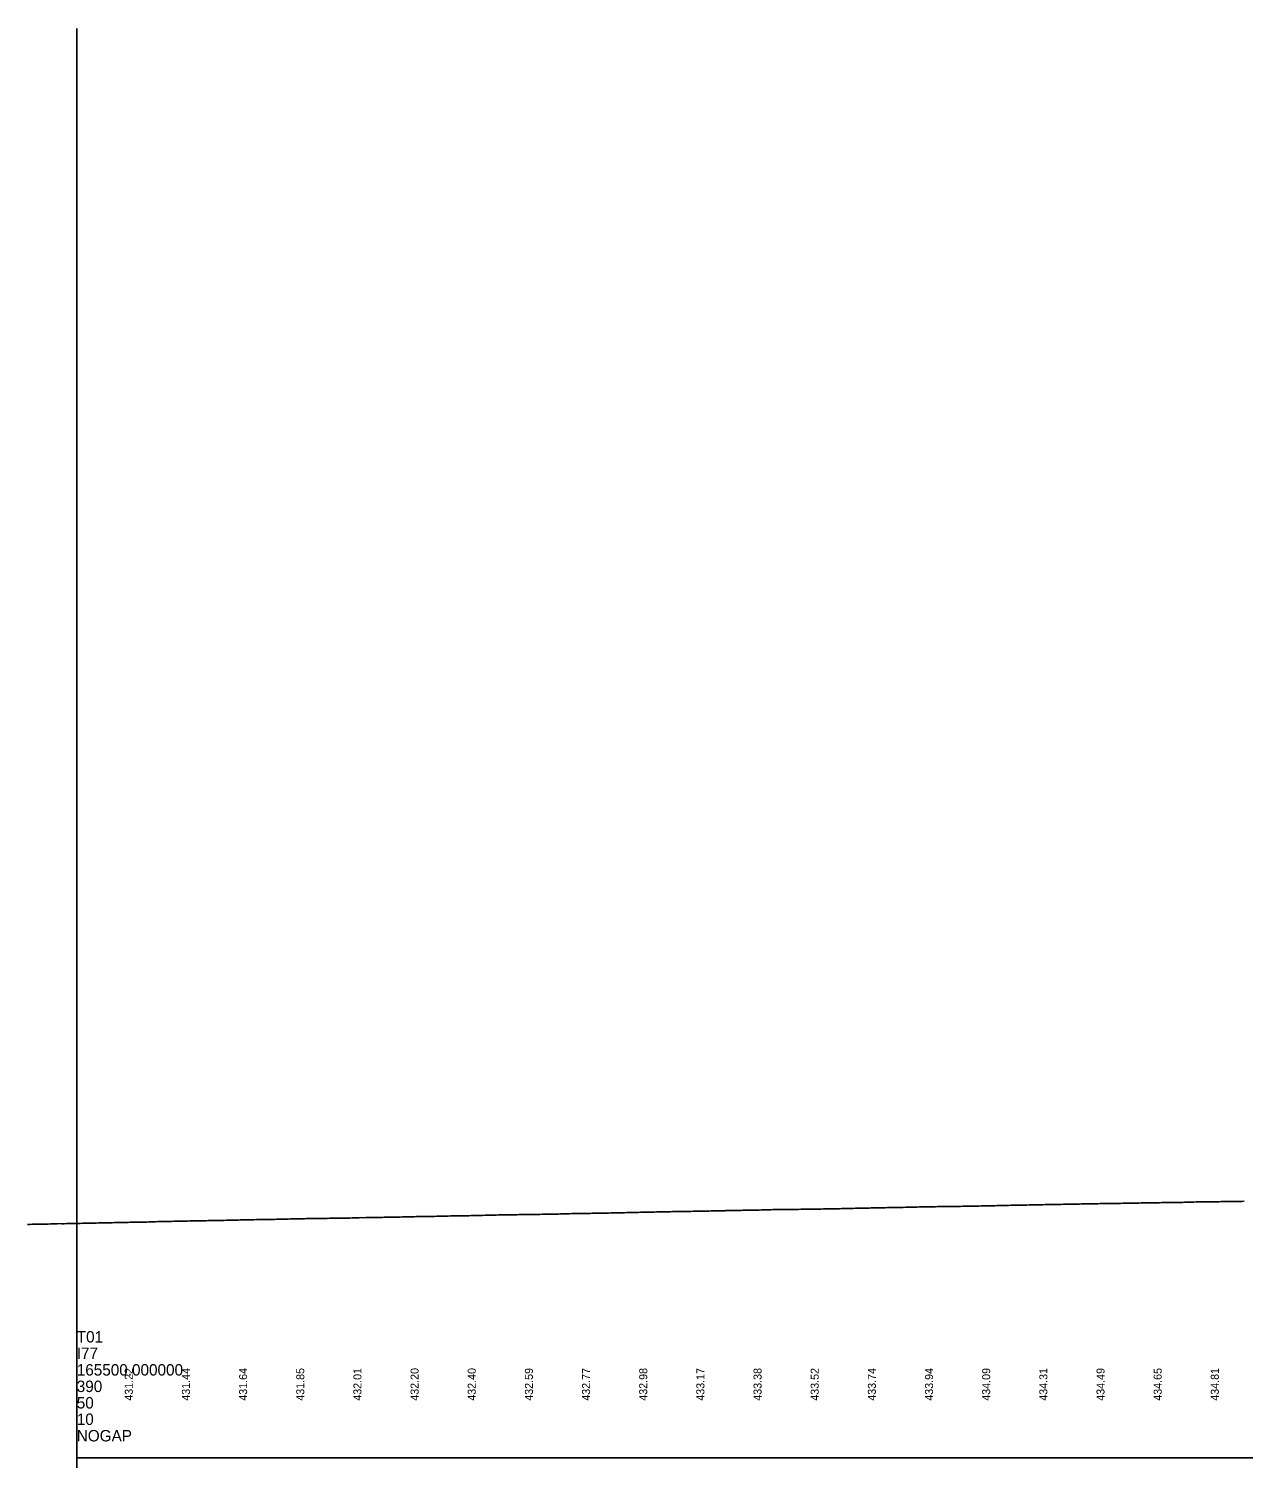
# Model space of a CAD drawing. Extents: x 2017200 to 2047700, y 854850 to 893350.
# Drawn here: x 2020458 to 2021520, y 856100 to 857350 of the extents above; entities that cross this region are included whole.
import ezdxf

# ---------------------------------------------------------------- set-up
doc = ezdxf.new("R2010")
doc.units = 0
for name, color, linetype in [('RD_DDB_Profile_EX', 7, 'Continuous'), ('RD_DDB_StripGrade', 7, 'Continuous'), ('RD_GPK_Profile_Cell', 7, 'Continuous')]:
    doc.layers.add(name, color=color, linetype=linetype)

msp = doc.modelspace()

# ---------------------------------------------------------------- linework, layer by layer
at = {"layer": 'RD_DDB_Profile_EX'}
msp.add_lwpolyline([(2020456.9, 856304.2), (2020458.9, 856304.2), (2020460.9, 856304.3), (2020462.9, 856304.3), (2020464.9, 856304.3), (2020466.9, 856304.4), (2020468.9, 856304.4), (2020471, 856304.5), (2020472.9, 856304.5), (2020474.9, 856304.5), (2020477, 856304.6), (2020479, 856304.6), (2020481, 856304.7), (2020482.9, 856304.7), (2020484.9, 856304.9), (2020487, 856304.8), (2020488.9, 856304.8), (2020490.9, 856304.9), (2020493, 856304.9), (2020495, 856305), (2020497.1, 856305), (2020499, 856305.1), (2020501, 856305.1), (2020503.1, 856305.1), (2020505, 856305.2), (2020507, 856305.2), (2020507.3, 856305.3), (2020508.9, 856305.3), (2020510.5, 856305.3), (2020510.9, 856305.3), (2020512.9, 856305.3), (2020513.2, 856305.3), (2020515, 856305.4), (2020516.9, 856305.4), (2020519.1, 856305.5), (2020520.6, 856305.5), (2020521, 856305.5), (2020523, 856305.5), (2020524.8, 856305.6), (2020525.1, 856305.6), (2020527, 856305.6), (2020529, 856305.7), (2020529.3, 856305.7), (2020531.1, 856305.7), (2020533, 856305.8), (2020534.9, 856305.8), (2020535.2, 856305.8), (2020536.9, 856305.8), (2020538.9, 856305.9), (2020539.4, 856305.9), (2020541, 856305.9), (2020543, 856305.9), (2020545.1, 856306), (2020546.6, 856306.1), (2020547, 856306.1), (2020549, 856306.1), (2020551.1, 856306.1), (2020553, 856306.1), (2020555.2, 856306.2), (2020557.1, 856306.3), (2020559, 856306.3), (2020561.1, 856306.3), (2020562.9, 856306.4), (2020564.9, 856306.5), (2020565.3, 856306.5), (2020567, 856306.5), (2020569, 856306.5), (2020570.9, 856306.6), (2020573, 856306.7), (2020575, 856306.7), (2020577.1, 856306.7), (2020579, 856306.7), (2020581, 856306.8), (2020583, 856306.8), (2020584.9, 856306.9), (2020585.7, 856306.9), (2020586.9, 856306.9), (2020589, 856307), (2020591, 856307), (2020593, 856307.1), (2020595, 856307.1), (2020597, 856307.1), (2020599, 856307.2), (2020601, 856307.2), (2020603.1, 856307.3), (2020605.1, 856307.2), (2020606.9, 856307.3), (2020609.1, 856307.3), (2020611, 856307.4), (2020613, 856307.4), (2020615, 856307.5), (2020617, 856307.5), (2020619, 856307.5), (2020621, 856307.5), (2020623, 856307.6), (2020625, 856307.6), (2020627.1, 856307.7), (2020629, 856307.7), (2020631, 856307.8), (2020631.9, 856307.8), (2020633, 856307.8), (2020635, 856307.9), (2020637, 856307.9), (2020639, 856307.9), (2020641.1, 856308), (2020643, 856308.1), (2020644.9, 856308.2), (2020645.3, 856308.2), (2020647, 856308.2), (2020649, 856308.2), (2020651.2, 856308.2), (2020653, 856308.3), (2020655, 856308.3), (2020657.1, 856308.4), (2020659, 856308.4), (2020661, 856308.4), (2020663, 856308.5), (2020665, 856308.5), (2020667.1, 856308.6), (2020669, 856308.6), (2020671.3, 856308.6), (2020673, 856308.6), (2020674.7, 856308.7), (2020675, 856308.7), (2020677.2, 856308.7), (2020679, 856308.8), (2020681, 856308.8), (2020683.1, 856308.9), (2020685, 856308.9), (2020687, 856309), (2020689.1, 856309), (2020691, 856309.1), (2020693.1, 856309.1), (2020695, 856309.2), (2020697, 856309.2), (2020699.1, 856309.2), (2020701, 856309.3), (2020703, 856309.3), (2020705, 856309.3), (2020707, 856309.4), (2020709, 856309.4), (2020711, 856309.4), (2020713, 856309.5), (2020715.1, 856309.5), (2020717, 856309.5), (2020719, 856309.5), (2020721, 856309.6), (2020723, 856309.6), (2020725.1, 856309.6), (2020727, 856309.6), (2020729, 856309.7), (2020731, 856309.7), (2020733, 856309.7), (2020735, 856309.8), (2020737, 856309.8), (2020739, 856309.8), (2020741, 856309.9), (2020742.9, 856309.9), (2020745, 856310), (2020747, 856310), (2020749, 856310.1), (2020751, 856310), (2020753, 856310.1), (2020755, 856310.1), (2020757, 856310.2), (2020758.7, 856310.2), (2020761, 856310.2), (2020763, 856310.2), (2020765, 856310.3), (2020767, 856310.3), (2020769, 856310.4), (2020771, 856310.4), (2020772.5, 856310.4), (2020773, 856310.4), (2020775, 856310.4), (2020777, 856310.5), (2020779, 856310.5), (2020781, 856310.6), (2020783, 856310.6), (2020785, 856310.7), (2020787, 856310.7), (2020789, 856310.8), (2020791, 856310.8), (2020792.2, 856310.8), (2020793, 856310.9), (2020795, 856310.9), (2020797, 856311), (2020799, 856311), (2020801, 856311), (2020803, 856311.1), (2020805, 856311.1), (2020807, 856311.2), (2020809, 856311.2), (2020809.6, 856311.2), (2020811, 856311.2), (2020813, 856311.2), (2020815, 856311.3), (2020817, 856311.3), (2020819, 856311.4), (2020821, 856311.4), (2020823, 856311.5), (2020825, 856311.5), (2020827, 856311.6), (2020829, 856311.6), (2020831, 856311.6), (2020833, 856311.6), (2020835, 856311.7), (2020836.4, 856311.7), (2020837, 856311.7), (2020839, 856311.8), (2020841, 856311.8), (2020843, 856311.8), (2020845, 856311.9), (2020847.1, 856311.9), (2020849, 856312), (2020851, 856312), (2020853, 856312.1), (2020855, 856312.1), (2020857.1, 856312.2), (2020859, 856312.2), (2020861, 856312.3), (2020863, 856312.3), (2020865, 856312.3), (2020867, 856312.4), (2020869, 856312.5), (2020871, 856312.5), (2020873, 856312.5), (2020875.1, 856312.6), (2020877, 856312.6), (2020879.2, 856312.6), (2020881.1, 856312.6), (2020883.1, 856312.7), (2020883.5, 856312.7), (2020885.2, 856312.7), (2020887.1, 856312.8), (2020889, 856312.8), (2020889.3, 856312.8), (2020891, 856312.8), (2020893, 856312.8), (2020895.1, 856312.9), (2020896.7, 856312.9), (2020897, 856312.9), (2020899, 856312.9), (2020901.1, 856313), (2020903, 856313), (2020905.1, 856313), (2020907, 856313.1), (2020909, 856313.1), (2020911.1, 856313.1), (2020913.1, 856313.2), (2020915, 856313.2), (2020915.3, 856313.2), (2020917, 856313.2), (2020919, 856313.3), (2020921.3, 856313.3), (2020923.1, 856313.4), (2020925, 856313.4), (2020927.2, 856313.4), (2020929.1, 856313.5), (2020931, 856313.5), (2020933.1, 856313.6), (2020935.1, 856313.6), (2020936.9, 856313.6), (2020937.3, 856313.6), (2020939.1, 856313.7), (2020941.1, 856313.7), (2020941.6, 856313.7), (2020943, 856313.7), (2020944.5, 856313.7), (2020945, 856313.7), (2020947, 856313.8), (2020947.4, 856313.8), (2020949.1, 856313.8), (2020950.7, 856313.9), (2020951, 856313.9), (2020953.3, 856313.9), (2020954.7, 856313.9), (2020955.1, 856313.9), (2020957.1, 856314), (2020958.9, 856314), (2020959.2, 856314), (2020961.1, 856314.1), (2020963.1, 856314.1), (2020963.5, 856314.1), (2020964.9, 856314.1), (2020965.2, 856314.1), (2020967.1, 856314.2), (2020969, 856314.2), (2020969.4, 856314.2), (2020971, 856314.3), (2020973, 856314.3), (2020975.1, 856314.3), (2020976.7, 856314.4), (2020977, 856314.4), (2020979, 856314.4), (2020981.1, 856314.5), (2020983, 856314.5), (2020985.2, 856314.6), (2020987.1, 856314.6), (2020989.1, 856314.7), (2020991.2, 856314.7), (2020993.1, 856314.8), (2020995, 856314.8), (2020995.3, 856314.8), (2020997, 856314.9), (2020998.7, 856314.9), (2020999, 856314.9), (2021001.1, 856314.9), (2021002.6, 856315), (2021003.1, 856315), (2021005, 856315), (2021007.1, 856315.1), (2021009.1, 856315.1), (2021011.3, 856315.1), (2021013.1, 856315.2), (2021015.1, 856315.2), (2021017.2, 856315.3), (2021019.1, 856315.3), (2021021.2, 856315.4), (2021023, 856315.4), (2021025, 856315.4), (2021027.1, 856315.5), (2021029, 856315.5), (2021031, 856315.6), (2021033.1, 856315.6), (2021035.1, 856315.6), (2021037, 856315.6), (2021039.1, 856315.7), (2021041.1, 856315.7), (2021043.3, 856315.7), (2021045.1, 856315.8), (2021047.1, 856315.8), (2021049.2, 856315.8), (2021051, 856315.9), (2021053.1, 856315.9), (2021055, 856316), (2021057, 856316), (2021058, 856316), (2021059, 856316), (2021061.1, 856316.1), (2021063.1, 856316.2), (2021065.1, 856316.2), (2021067, 856316.2), (2021067.7, 856316.3), (2021069.1, 856316.3), (2021071.1, 856316.3), (2021073.1, 856316.4), (2021075, 856316.4), (2021075.3, 856316.4), (2021077, 856316.5), (2021078.7, 856316.5), (2021079, 856316.5), (2021079.6, 856316.5), (2021081.1, 856316.5), (2021082.6, 856316.6), (2021083, 856316.6), (2021085, 856316.6), (2021087.1, 856316.7), (2021089.1, 856316.7), (2021091.2, 856316.7), (2021093.1, 856316.8), (2021095, 856316.8), (2021097, 856316.8), (2021099, 856316.9), (2021101.1, 856316.9), (2021103, 856316.9), (2021105, 856317), (2021107.1, 856317), (2021109, 856317.1), (2021111, 856317.1), (2021113.1, 856317.1), (2021115.1, 856317.2), (2021117.3, 856317.2), (2021118.8, 856317.2), (2021119.2, 856317.2), (2021121.1, 856317.3), (2021122.9, 856317.3), (2021123.3, 856317.3), (2021125.2, 856317.3), (2021127.1, 856317.3), (2021127.6, 856317.3), (2021129, 856317.3), (2021130.5, 856317.3), (2021131, 856317.3), (2021133.3, 856317.4), (2021135, 856317.4), (2021137, 856317.4), (2021139.1, 856317.4), (2021141, 856317.5), (2021143, 856317.5), (2021145, 856317.6), (2021147, 856317.6), (2021149.1, 856317.6), (2021151.1, 856317.6), (2021153.1, 856317.7), (2021155.1, 856317.7), (2021157.1, 856317.7), (2021159.2, 856317.8), (2021161.1, 856317.8), (2021163, 856317.9), (2021165.2, 856317.9), (2021167.1, 856317.9), (2021169, 856318), (2021171.1, 856318), (2021173.1, 856318.1), (2021175, 856318.1), (2021177.1, 856318.2), (2021179.1, 856318.2), (2021181.1, 856318.3), (2021183.1, 856318.3), (2021185.1, 856318.4), (2021187, 856318.4), (2021189, 856318.5), (2021191, 856318.5), (2021193.1, 856318.5), (2021195, 856318.6), (2021197.1, 856318.6), (2021199.1, 856318.7), (2021201.1, 856318.7), (2021203.1, 856318.7), (2021205.1, 856318.8), (2021207.2, 856318.8), (2021209.1, 856318.9), (2021211.1, 856318.9), (2021213.2, 856318.9), (2021215, 856319), (2021217, 856319), (2021219.1, 856319.1), (2021221.1, 856319.1), (2021223, 856319.1), (2021225.1, 856319.2), (2021227.1, 856319.3), (2021229.1, 856319.3), (2021231.1, 856319.3), (2021233.3, 856319.4), (2021235.2, 856319.4), (2021237.1, 856319.5), (2021239.3, 856319.5), (2021241, 856319.5), (2021243, 856319.6), (2021244.8, 856319.6), (2021245.2, 856319.6), (2021246.7, 856319.7), (2021247.1, 856319.7), (2021249.1, 856319.7), (2021251.1, 856319.7), (2021253.1, 856319.8), (2021255.1, 856319.8), (2021257.1, 856319.8), (2021259.1, 856319.8), (2021261.1, 856319.9), (2021262.1, 856319.9), (2021263.1, 856319.9), (2021265.1, 856319.9), (2021266.6, 856320), (2021267, 856320), (2021269, 856320), (2021271.2, 856320), (2021273.1, 856320), (2021275.1, 856320.1), (2021277.2, 856320.1), (2021279.1, 856320.1), (2021281.1, 856320.1), (2021281.5, 856320.1), (2021282.8, 856320.2), (2021283.2, 856320.2), (2021285.1, 856320.2), (2021287, 856320.2), (2021287.4, 856320.2), (2021289.2, 856320.2), (2021291.1, 856320.3), (2021291.6, 856320.3), (2021293.1, 856320.3), (2021294.7, 856320.3), (2021295, 856320.3), (2021297.2, 856320.4), (2021299.1, 856320.4), (2021301.1, 856320.5), (2021302.2, 856320.5), (2021303.1, 856320.5), (2021305.1, 856320.6), (2021307.1, 856320.6), (2021309.1, 856320.7), (2021311.1, 856320.7), (2021312.1, 856320.7), (2021313.1, 856320.8), (2021315.1, 856320.8), (2021317.1, 856320.9), (2021319.2, 856320.9), (2021321, 856320.9), (2021323.3, 856321), (2021325.1, 856321), (2021327.1, 856321.1), (2021329.1, 856321.1), (2021331.1, 856321.1), (2021333.1, 856321.2), (2021335.2, 856321.2), (2021337.1, 856321.3), (2021339.1, 856321.3), (2021341.1, 856321.3), (2021341.8, 856321.4), (2021343.1, 856321.4), (2021345.1, 856321.4), (2021347.1, 856321.5), (2021349.1, 856321.5), (2021351.1, 856321.6), (2021353.1, 856321.6), (2021355.1, 856321.6), (2021356.6, 856321.7), (2021357.1, 856321.7), (2021359.1, 856321.7), (2021361.1, 856321.7), (2021363.1, 856321.8), (2021365.1, 856321.8), (2021367.1, 856321.9), (2021369.1, 856321.9), (2021371.1, 856322), (2021373.3, 856322), (2021375.1, 856322), (2021377.1, 856322), (2021378.8, 856322.1), (2021381.1, 856322.1), (2021383.1, 856322.2), (2021385.1, 856322.2), (2021387.1, 856322.2), (2021389.1, 856322.2), (2021391.1, 856322.3), (2021393.2, 856322.3), (2021395.1, 856322.4), (2021397.1, 856322.4), (2021399.1, 856322.4), (2021401.1, 856322.4), (2021403.2, 856322.5), (2021405.1, 856322.5), (2021407.1, 856322.5), (2021409.1, 856322.6), (2021411.1, 856322.6), (2021413.1, 856322.6), (2021415.1, 856322.7), (2021417.1, 856322.7), (2021419.2, 856322.8), (2021421.1, 856322.8), (2021423.1, 856322.8), (2021425.2, 856322.9), (2021427.1, 856322.9), (2021429.3, 856322.9), (2021431.1, 856323), (2021433.1, 856323), (2021435.3, 856323), (2021437.1, 856323.1), (2021439.1, 856323.1), (2021441.2, 856323.1), (2021443.1, 856323.1), (2021445.1, 856323.2), (2021445.5, 856323.2), (2021446.9, 856323.2), (2021447.2, 856323.2), (2021449.1, 856323.3), (2021451.3, 856323.3), (2021453.2, 856323.3), (2021455.1, 856323.3), (2021455.5, 856323.3), (2021457.1, 856323.4), (2021459.1, 856323.4), (2021461.1, 856323.4), (2021463.1, 856323.5), (2021464.8, 856323.5), (2021467.2, 856323.5), (2021469.1, 856323.6), (2021471.1, 856323.6), (2021473.1, 856323.7), (2021475.1, 856323.7), (2021477.2, 856323.7), (2021479.1, 856323.8), (2021481.1, 856323.8), (2021483.3, 856323.8), (2021485.1, 856323.9), (2021487.1, 856323.9), (2021489.1, 856323.9), (2021491.1, 856324), (2021493.1, 856324), (2021495.1, 856324), (2021497.1, 856324), (2021499.2, 856324), (2021501.1, 856324.1), (2021503.1, 856324.1), (2021505.1, 856324.2), (2021507.1, 856324.2), (2021509.2, 856324.2), (2021511.1, 856324.3), (2021513.1, 856324.3), (2021515.2, 856324.3), (2021517.1, 856324.3), (2021519.1, 856324.3), (2021521.2, 856324.5)], dxfattribs=at)
at = {"layer": 'RD_GPK_Profile_Cell'}
for q in [(2020500, 857350), (2047700, 856100), (2020500, 854850)]:
    msp.add_line((2020500, 856100), q, dxfattribs=at)

# ---------------------------------------------------------------- texts
at = {"layer": 'RD_DDB_StripGrade'}
for s, p in [('431.22', (2020549, 856150)), ('431.44', (2020599, 856150)), ('431.64', (2020649, 856150)), ('431.85', (2020699, 856150)), ('432.01', (2020749, 856150)), ('432.20', (2020799, 856150)), ('432.40', (2020849, 856150)), ('432.59', (2020899, 856150)), ('432.77', (2020949, 856150)), ('432.98', (2020999, 856150)), ('433.17', (2021049, 856150)), ('433.38', (2021099, 856150)), ('433.52', (2021149, 856150)), ('433.74', (2021199, 856150)), ('433.94', (2021249, 856150)), ('434.09', (2021299, 856150)), ('434.31', (2021349, 856150)), ('434.49', (2021399, 856150)), ('434.65', (2021449, 856150)), ('434.81', (2021499, 856150))]:
    msp.add_text(s, height=7, rotation=90, dxfattribs=at).set_placement(p)
at = {"layer": 'RD_GPK_Profile_Cell'}
for s, p in [('T01', (2020500, 856200.9)), ('I77', (2020500, 856186.5)), ('165500.000000', (2020500, 856172)), ('390', (2020500, 856157.6)), ('50', (2020500, 856143.2)), ('10', (2020500, 856128.8)), ('NOGAP', (2020500, 856114.4))]:
    msp.add_text(s, height=10, dxfattribs=at).set_placement(p)

doc.saveas('drawing.dxf')
